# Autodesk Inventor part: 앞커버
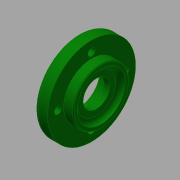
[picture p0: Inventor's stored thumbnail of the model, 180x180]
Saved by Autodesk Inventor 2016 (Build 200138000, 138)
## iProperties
Created: 2015-12
Part Number: 앞커버
Material: 알루미늄 6061
Document SubType Name: Modeling
Designer: mduedu
Density: 2.71 g/cm^3
Appearance: 진녹색
Author: mduedu
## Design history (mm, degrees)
sketch "스케치1"
  geometry: L1 (0, 0)-(14, 0); L2 (14, 0)-(14, 17.5); L3 (14, 17.5)-(8, 17.5); L4 (8, 17.5)-(8, 27.5); L5 (8, 27.5)-(0, 27.5); L6 (0, 27.5)-(0, 0)
  constraints: 12 end point, 4 parallel, 1 horizontal, 1 perpendicular
  dimensions: "d0" = 14 distance between parallel lines of L2 L6; "d2" = 8 distance of L4.end L5.end; "d3" = 55 diameter of L5 L1; "d4" = 35 diameter of L3 L1
revolve "회전1" sketch "스케치1" stored, may be unused: angle "d5" = 90 deg
hole "구멍1" diameter "d8" = 30; stored, may be unused: countersink angle "d12" = 90 deg, drill point angle "d14" = 0 deg; dims "d6" = 10, "d7" = 10, "d9" = 6, "d10" = 4, "d11" = 2, "d13" = 3
hole "구멍2" diameter "d17" = 25; stored, may be unused: countersink angle "d21" = 90 deg, drill point angle "d23" = 0 deg; dims "d15" = 10, "d16" = 10, "d18" = 6, "d19" = 4, "d20" = 2, "d22" = 7.3
hole "구멍3" diameter "d26" = 16.5; stored, may be unused: countersink angle "d30" = 90 deg, drill point angle "d32" = 0 deg; dims "d24" = 10, "d25" = 10, "d27" = 6, "d28" = 4, "d29" = 2, "d31" = 7.3
fillet "모깎기1" dims "d33" = 0.3
chamfer "모따기1" distance "d34" = 1; stored, may be unused: second distance "d35" = 2, angle "d36" = 30 deg
fillet "모깎기2" dims "d37" = 3
fillet "모깎기3" dims "d38" = 2
chamfer "모따기2" distance "d39" = 0.5; stored, may be unused: second distance "d40" = 2, angle "d41" = 45 deg
sketch "스케치2" dims "d42" = 42
  geometry: 9 further points
  constraints: 3 coincident, 2 vertical alignment, 9 other
  dimensions: "d46" = 360 deg dimension on point (0, 0) point (0, 21) (derived)
sketch "스케치3"
  geometry: 4 further points
hole "구멍4" sketch "스케치3" at (-21, 0), (0, -21), (21, 0), (0, 21) diameter "d50" = 4.5; stored, may be unused: countersink angle "d54" = 90 deg, drill point angle "d56" = 0 deg; dims "d51" = 6, "d52" = 8, "d53" = 4.6, "d55" = 8
node "솔리드1"
